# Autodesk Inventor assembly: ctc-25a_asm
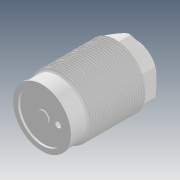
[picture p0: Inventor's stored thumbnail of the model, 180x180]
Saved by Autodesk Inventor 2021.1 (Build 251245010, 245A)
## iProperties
Created: 2018-08
Part Number: ctc-25a_asm
Description: STEP AP203
Document SubType Name: Assembly
Designer: user
Title: ctc-25a_asm.STEP
Revision Number: ÈÎºÎ
Sending System: SolidWorks 2015
Preprocessor: SwSTEP 2.0
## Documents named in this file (6)
- D:\Vault_2016\Projekty\Clamptek\Hydraulic\CTC\Inventor\ctc-25a\ctc-25a_asm.iam
- D:\Vault_2016\Projekty\Clamptek\Hydraulic\CTC\Inventor\ctc-25a\CTC-25BT.ipt
- D:\Vault_2016\Projekty\Clamptek\Hydraulic\CTC\Inventor\ctc-25a\CTC-25AHSG.ipt
- D:\Vault_2016\Projekty\Clamptek\Hydraulic\CTC\Inventor\ctc-25a\CTC-25HG.ipt
- D:\Vault_2016\Projekty\Clamptek\Hydraulic\CTC\Inventor\ctc-25a\CTC-25MD.ipt
- D:\Vault_2016\Projekty\Clamptek\Hydraulic\CTC\Inventor\ctc-25a\CTC-25DP.ipt
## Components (5 placed, 5 different names)
1. CTC-25BT_1
2. CTC-25AHSG_2
3. CTC-25HG_3
4. CTC-25MD_4
5. CTC-25DP_5
